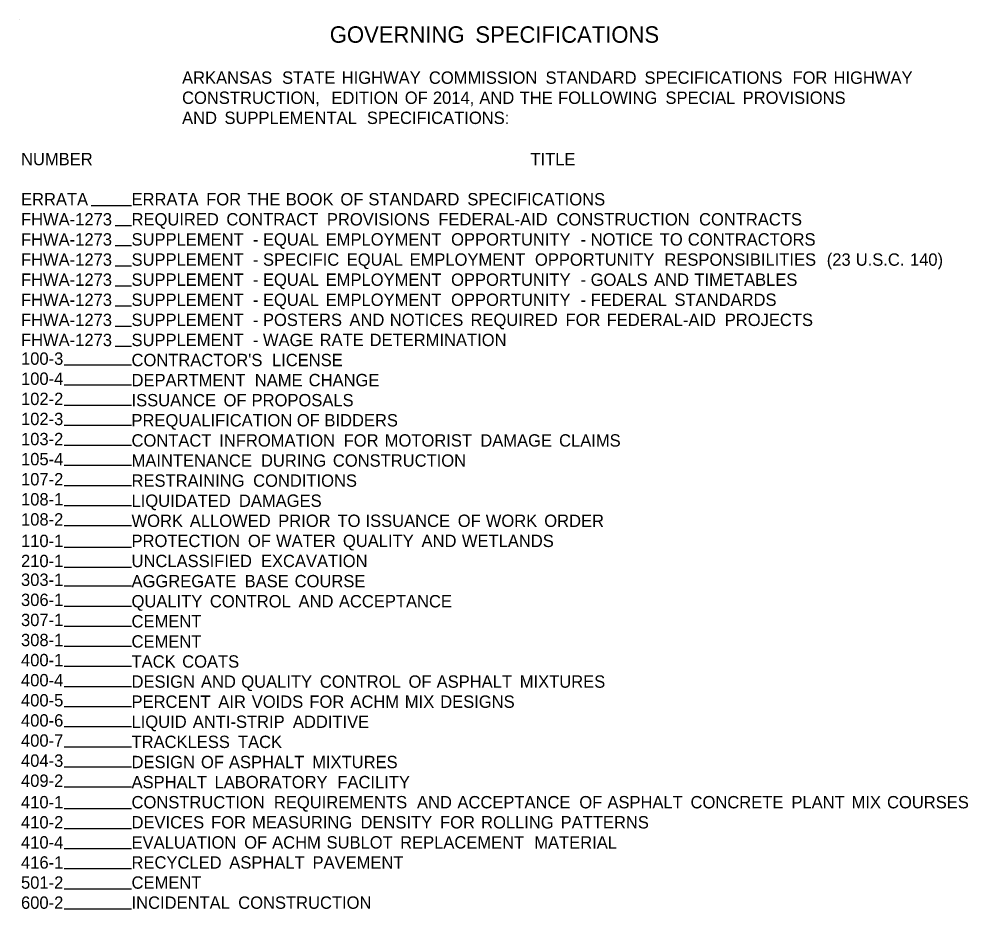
# Model space of a CAD drawing. Extents: x 1334737.6 to 1334769.5, y 402732.2 to 402752.6.
# Drawn here: x 1334739.51 to 1334750.33, y 402742.43 to 402752.57 of the extents above; entities that cross this region are included whole.
import ezdxf

# ---------------------------------------------------------------- set-up
doc = ezdxf.new("R2010")
doc.units = 0
doc.layers.add('Default', color=7, linetype='Continuous')

msp = doc.modelspace()

# ---------------------------------------------------------------- linework, layer by layer
at = {"layer": 'Default'}
for p, q in [((1334739.513, 402752.574), (1334739.513, 402752.574)), ((1334740.335, 402750.449), (1334740.796, 402750.449)), ((1334740.61, 402750.22), (1334740.797, 402750.22)), ((1334740.61, 402749.991), (1334740.797, 402749.991)), ((1334740.61, 402749.761), (1334740.797, 402749.761)), ((1334740.61, 402749.532), (1334740.797, 402749.532)), ((1334740.61, 402749.303), (1334740.797, 402749.303)), ((1334740.61, 402749.074), (1334740.797, 402749.074)), ((1334740.61, 402748.845), (1334740.797, 402748.845)), ((1334740.029, 402748.632), (1334740.796, 402748.632)), ((1334740.029, 402748.403), (1334740.796, 402748.403)), ((1334740.029, 402748.173), (1334740.796, 402748.173)), ((1334740.029, 402747.944), (1334740.796, 402747.944)), ((1334740.029, 402747.715), (1334740.796, 402747.715)), ((1334740.029, 402747.486), (1334740.796, 402747.486)), ((1334740.029, 402747.257), (1334740.796, 402747.257)), ((1334740.029, 402747.028), (1334740.796, 402747.028)), ((1334740.029, 402746.799), (1334740.796, 402746.799)), ((1334740.029, 402746.554), (1334740.796, 402746.554)), ((1334740.029, 402746.325), (1334740.796, 402746.325)), ((1334740.029, 402746.111), (1334740.796, 402746.111)), ((1334740.029, 402745.882), (1334740.796, 402745.882)), ((1334740.029, 402745.653), (1334740.796, 402745.653)), ((1334740.029, 402745.424), (1334740.796, 402745.424)), ((1334740.029, 402745.195), (1334740.796, 402745.195)), ((1334740.029, 402744.966), (1334740.796, 402744.966)), ((1334740.029, 402744.737), (1334740.796, 402744.737)), ((1334740.029, 402744.507), (1334740.796, 402744.507)), ((1334740.029, 402744.278), (1334740.796, 402744.278)), ((1334740.029, 402744.049), (1334740.796, 402744.049)), ((1334740.029, 402743.82), (1334740.796, 402743.82)), ((1334740.029, 402743.575), (1334740.796, 402743.575)), ((1334740.029, 402743.346), (1334740.796, 402743.346)), ((1334740.029, 402743.117), (1334740.796, 402743.117)), ((1334740.029, 402742.888), (1334740.796, 402742.888)), ((1334740.029, 402742.659), (1334740.796, 402742.659)), ((1334740.029, 402742.43), (1334740.796, 402742.43))]:
    msp.add_line(p, q, dxfattribs=at)

# ---------------------------------------------------------------- texts
for s, height, p in [('GOVERNING', 0.188, (1334743.056, 402752.303)), (' SPECIFICATIONS', 0.188, (1334744.646, 402752.303)), ('           ARKANSAS', 0.141, (1334740.796, 402751.835)), (' STATE', 0.141, (1334742.46, 402751.835)), (' HIGHWAY', 0.141, (1334743.14, 402751.835)), (' COMMISSION', 0.141, (1334744.134, 402751.835)), (' STANDARD', 0.141, (1334745.464, 402751.835)), (' SPECIFICATIONS', 0.141, (1334746.592, 402751.835)), (' FOR', 0.141, (1334748.279, 402751.835)), (' HIGHWAY', 0.141, (1334748.747, 402751.835)), ('           CONSTRUCTION,', 0.141, (1334740.796, 402751.606)), (' EDITION', 0.141, (1334743.022, 402751.606)), (' OF', 0.141, (1334743.859, 402751.606)), (' 2014,', 0.141, (1334744.179, 402751.606)), (' AND', 0.141, (1334744.709, 402751.606)), (' THE', 0.141, (1334745.169, 402751.606)), (' FOLLOWING', 0.141, (1334745.607, 402751.606)), (' SPECIAL', 0.141, (1334746.831, 402751.606)), (' PROVISIONS', 0.141, (1334747.711, 402751.606)), ('           AND', 0.141, (1334740.796, 402751.377)), (' SUPPLEMENTAL', 0.141, (1334741.803, 402751.377)), (' SPECIFICATIONS:', 0.141, (1334743.427, 402751.377)), ('NUMBER', 0.141, (1334739.536, 402750.907)), ('TITLE', 0.141, (1334745.344, 402750.907)), ('ERRATA', 0.141, (1334739.536, 402750.449)), ('ERRATA', 0.141, (1334740.796, 402750.449)), (' FOR', 0.141, (1334741.595, 402750.449)), (' THE', 0.141, (1334742.063, 402750.449)), (' BOOK', 0.141, (1334742.502, 402750.449)), (' OF', 0.141, (1334743.125, 402750.449)), (' STANDARD', 0.141, (1334743.444, 402750.449)), (' SPECIFICATIONS', 0.141, (1334744.572, 402750.449)), ('FHWA-1273', 0.141, (1334739.536, 402750.22)), ('REQUIRED', 0.141, (1334740.796, 402750.22)), (' CONTRACT', 0.141, (1334741.825, 402750.22)), (' PROVISIONS', 0.141, (1334742.971, 402750.22)), (' FEDERAL-AID', 0.141, (1334744.241, 402750.22)), (' CONSTRUCTION', 0.141, (1334745.588, 402750.22)), (' CONTRACTS', 0.141, (1334747.214, 402750.22)), ('FHWA-1273', 0.141, (1334739.536, 402749.991)), ('SUPPLEMENT', 0.141, (1334740.796, 402749.991)), (' EQUAL', 0.141, (1334742.242, 402749.991)), (' EMPLOYMENT', 0.141, (1334742.957, 402749.991)), (' OPPORTUNITY', 0.141, (1334744.387, 402749.991)), (' NOTICE', 0.141, (1334745.978, 402749.991)), (' TO', 0.141, (1334746.766, 402749.991)), (' CONTRACTORS', 0.141, (1334747.086, 402749.991)), (' -', 0.141, (1334742.128, 402749.991)), (' -', 0.141, (1334745.864, 402749.991)), ('FHWA-1273', 0.141, (1334739.536, 402749.761)), ('SUPPLEMENT', 0.141, (1334740.796, 402749.761)), (' SPECIFIC', 0.141, (1334742.242, 402749.761)), (' EQUAL', 0.141, (1334743.197, 402749.761)), (' EMPLOYMENT', 0.141, (1334743.913, 402749.761)), (' OPPORTUNITY', 0.141, (1334745.343, 402749.761)), (' RESPONSIBILITIES', 0.141, (1334746.819, 402749.761)), (' (23', 0.141, (1334748.67, 402749.761)), (' U.S.C.', 0.141, (1334749, 402749.761)), (' 140)', 0.141, (1334749.618, 402749.761)), (' -', 0.141, (1334742.128, 402749.761)), ('FHWA-1273', 0.141, (1334739.536, 402749.532)), ('SUPPLEMENT', 0.141, (1334740.796, 402749.532)), (' EQUAL', 0.141, (1334742.242, 402749.532)), (' EMPLOYMENT', 0.141, (1334742.957, 402749.532)), (' OPPORTUNITY', 0.141, (1334744.387, 402749.532)), (' GOALS', 0.141, (1334745.978, 402749.532)), (' AND', 0.141, (1334746.701, 402749.532)), (' TIMETABLES', 0.141, (1334747.161, 402749.532)), (' -', 0.141, (1334742.128, 402749.532)), (' -', 0.141, (1334745.864, 402749.532)), ('FHWA-1273', 0.141, (1334739.536, 402749.303)), ('SUPPLEMENT', 0.141, (1334740.796, 402749.303)), (' EQUAL', 0.141, (1334742.242, 402749.303)), (' EMPLOYMENT', 0.141, (1334742.957, 402749.303)), (' OPPORTUNITY', 0.141, (1334744.387, 402749.303)), (' FEDERAL', 0.141, (1334745.978, 402749.303)), (' STANDARDS', 0.141, (1334746.934, 402749.303)), (' -', 0.141, (1334742.128, 402749.303)), (' -', 0.141, (1334745.864, 402749.303)), ('FHWA-1273', 0.141, (1334739.536, 402749.074)), ('SUPPLEMENT', 0.141, (1334740.796, 402749.074)), (' -', 0.141, (1334742.128, 402749.074)), (' POSTERS', 0.141, (1334742.242, 402749.074)), (' AND', 0.141, (1334743.228, 402749.074)), (' NOTICES', 0.141, (1334743.688, 402749.074)), (' REQUIRED', 0.141, (1334744.608, 402749.074)), (' FOR', 0.141, (1334745.692, 402749.074)), (' FEDERAL-AID', 0.141, (1334746.16, 402749.074)), (' PROJECTS', 0.141, (1334747.507, 402749.074)), ('FHWA-1273', 0.141, (1334739.536, 402748.845)), ('SUPPLEMENT', 0.141, (1334740.796, 402748.845)), (' -', 0.141, (1334742.128, 402748.845)), (' WAGE', 0.141, (1334742.242, 402748.845)), (' RATE', 0.141, (1334742.888, 402748.845)), (' DETERMINATION', 0.141, (1334743.458, 402748.845)), ('100-3', 0.141, (1334739.536, 402748.632)), ("CONTRACTOR'S", 0.141, (1334740.796, 402748.616)), (' LICENSE', 0.141, (1334742.345, 402748.616)), ('100-4', 0.141, (1334739.536, 402748.403)), ('DEPARTMENT', 0.141, (1334740.796, 402748.387)), (' NAME', 0.141, (1334742.149, 402748.387)), (' CHANGE', 0.141, (1334742.763, 402748.387)), ('102-2', 0.141, (1334739.536, 402748.173)), ('ISSUANCE', 0.141, (1334740.796, 402748.158)), (' OF', 0.141, (1334741.793, 402748.158)), (' PROPOSALS', 0.141, (1334742.112, 402748.158)), ('102-3 ', 0.141, (1334739.536, 402747.944)), ('PREQUALIFICATION OF BIDDERS', 0.141, (1334740.795, 402747.929)), ('103-2', 0.141, (1334739.536, 402747.715)), ('CONTACT', 0.141, (1334740.796, 402747.699)), (' INFROMATION', 0.141, (1334741.744, 402747.699)), (' FOR', 0.141, (1334743.162, 402747.699)), (' MOTORIST', 0.141, (1334743.63, 402747.699)), (' DAMAGE', 0.141, (1334744.72, 402747.699)), (' CLAIMS', 0.141, (1334745.618, 402747.699)), ('105-4', 0.141, (1334739.536, 402747.486)), ('MAINTENANCE', 0.141, (1334740.796, 402747.47)), (' DURING', 0.141, (1334742.219, 402747.47)), (' CONSTRUCTION', 0.141, (1334743.039, 402747.47)), ('107-2', 0.141, (1334739.536, 402747.257)), ('RESTRAINING', 0.141, (1334740.796, 402747.241)), (' CONDITIONS', 0.141, (1334742.13, 402747.241)), ('108-1', 0.141, (1334739.536, 402747.028)), ('LIQUIDATED', 0.141, (1334740.796, 402747.012)), (' DAMAGES', 0.141, (1334741.968, 402747.012)), ('108-2', 0.141, (1334739.536, 402746.799)), ('WORK', 0.141, (1334740.796, 402746.783)), (' ALLOWED', 0.141, (1334741.408, 402746.783)), (' PRIOR', 0.141, (1334742.416, 402746.783)), (' TO', 0.141, (1334743.092, 402746.783)), (' ISSUANCE', 0.141, (1334743.411, 402746.783)), (' OF', 0.141, (1334744.463, 402746.783)), (' WORK', 0.141, (1334744.782, 402746.783)), (' ORDER', 0.141, (1334745.449, 402746.783)), ('110-1', 0.141, (1334739.536, 402746.554)), ('PROTECTION', 0.141, (1334740.796, 402746.554)), (' OF', 0.141, (1334742.071, 402746.554)), (' WATER', 0.141, (1334742.391, 402746.554)), (' QUALITY', 0.141, (1334743.154, 402746.554)), (' AND', 0.141, (1334744.05, 402746.554)), (' WETLANDS', 0.141, (1334744.51, 402746.554)), ('210-1', 0.141, (1334739.536, 402746.325)), ('UNCLASSIFIED', 0.141, (1334740.796, 402746.325)), (' EXCAVATION', 0.141, (1334742.219, 402746.325)), ('303-1', 0.141, (1334739.536, 402746.111)), ('AGGREGATE', 0.141, (1334740.796, 402746.095)), (' BASE', 0.141, (1334742.033, 402746.095)), (' COURSE', 0.141, (1334742.603, 402746.095)), ('306-1', 0.141, (1334739.536, 402745.882)), ('QUALITY', 0.141, (1334740.796, 402745.866)), (' CONTROL', 0.141, (1334741.637, 402745.866)), (' AND', 0.141, (1334742.648, 402745.866)), (' ACCEPTANCE', 0.141, (1334743.108, 402745.866)), ('307-1', 0.141, (1334739.536, 402745.653)), ('CEMENT', 0.141, (1334740.796, 402745.637)), ('308-1', 0.141, (1334739.536, 402745.424)), ('CEMENT', 0.141, (1334740.796, 402745.408)), ('400-1', 0.141, (1334739.536, 402745.195)), ('TACK', 0.141, (1334740.796, 402745.179)), (' COATS', 0.141, (1334741.321, 402745.179)), ('400-4', 0.141, (1334739.536, 402744.966)), ('DESIGN', 0.141, (1334740.796, 402744.95)), (' AND', 0.141, (1334741.535, 402744.95)), (' QUALITY', 0.141, (1334741.995, 402744.95)), (' CONTROL', 0.141, (1334742.891, 402744.95)), (' OF', 0.141, (1334743.902, 402744.95)), (' ASPHALT', 0.141, (1334744.222, 402744.95)), (' MIXTURES', 0.141, (1334745.17, 402744.95)), ('400-5', 0.141, (1334739.536, 402744.737)), ('PERCENT', 0.141, (1334740.796, 402744.721)), (' AIR', 0.141, (1334741.733, 402744.721)), (' VOIDS', 0.141, (1334742.114, 402744.721)), (' FOR', 0.141, (1334742.771, 402744.721)), (' ACHM', 0.141, (1334743.239, 402744.721)), (' MIX', 0.141, (1334743.859, 402744.721)), (' DESIGNS', 0.141, (1334744.263, 402744.721)), ('400-6', 0.141, (1334739.536, 402744.507)), ('LIQUID', 0.141, (1334740.796, 402744.492)), (' ANTI-STRIP', 0.141, (1334741.442, 402744.492)), (' ADDITIVE', 0.141, (1334742.583, 402744.492)), ('400-7', 0.141, (1334739.536, 402744.278)), ('TRACKLESS', 0.141, (1334740.796, 402744.263)), (' TACK', 0.141, (1334741.957, 402744.263)), ('404-3', 0.141, (1334739.536, 402744.049)), ('DESIGN', 0.141, (1334740.796, 402744.033)), (' OF', 0.141, (1334741.535, 402744.033)), (' ASPHALT', 0.141, (1334741.854, 402744.033)), (' MIXTURES', 0.141, (1334742.803, 402744.033)), ('409-2', 0.141, (1334739.536, 402743.82)), ('ASPHALT', 0.141, (1334740.796, 402743.804)), (' LABORATORY', 0.141, (1334741.69, 402743.804)), (' FACILITY', 0.141, (1334743.09, 402743.804)), ('410-1', 0.141, (1334739.536, 402743.575)), ('CONSTRUCTION', 0.141, (1334740.796, 402743.575)), (' REQUIREMENTS', 0.141, (1334742.367, 402743.575)), (' AND', 0.141, (1334743.998, 402743.575)), (' ACCEPTANCE', 0.141, (1334744.459, 402743.575)), (' OF', 0.141, (1334745.849, 402743.575)), (' ASPHALT', 0.141, (1334746.169, 402743.575)), (' CONCRETE', 0.141, (1334747.117, 402743.575)), (' PLANT', 0.141, (1334748.267, 402743.575)), (' MIX', 0.141, (1334748.953, 402743.575)), (' COURSES', 0.141, (1334749.357, 402743.575)), ('410-2', 0.141, (1334739.536, 402743.346)), ('DEVICES', 0.141, (1334740.796, 402743.346)), (' FOR', 0.141, (1334741.651, 402743.346)), (' MEASURING', 0.141, (1334742.118, 402743.346)), (' DENSITY', 0.141, (1334743.354, 402743.346)), (' FOR', 0.141, (1334744.261, 402743.346)), (' ROLLING', 0.141, (1334744.729, 402743.346)), (' PATTERNS', 0.141, (1334745.636, 402743.346)), ('410-4', 0.141, (1334739.536, 402743.117)), ('EVALUATION', 0.141, (1334740.796, 402743.117)), (' OF', 0.141, (1334742.028, 402743.117)), (' ACHM', 0.141, (1334742.347, 402743.117)), (' SUBLOT', 0.141, (1334742.967, 402743.117)), (' REPLACEMENT', 0.141, (1334743.806, 402743.117)), (' MATERIAL', 0.141, (1334745.335, 402743.117)), ('416-1', 0.141, (1334739.536, 402742.888)), ('RECYCLED', 0.141, (1334740.796, 402742.888)), (' ASPHALT', 0.141, (1334741.858, 402742.888)), (' PAVEMENT', 0.141, (1334742.807, 402742.888)), ('501-2', 0.141, (1334739.536, 402742.659)), ('CEMENT', 0.141, (1334740.796, 402742.659)), ('600-2', 0.141, (1334739.536, 402742.43)), ('INCIDENTAL', 0.141, (1334740.796, 402742.43)), (' CONSTRUCTION', 0.141, (1334741.96, 402742.43))]:
    msp.add_text(s, height=height, dxfattribs=at).set_placement(p)

doc.saveas('drawing.dxf')
